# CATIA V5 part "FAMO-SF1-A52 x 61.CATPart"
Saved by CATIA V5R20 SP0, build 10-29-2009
Part number: FAMO-SF1-A52 x 61
Definition: NONE
Nomenclature: FAMO-SF1-A52 x 61
Source: Unknown
Description: FAMO-SF1-A52 x 61
Bounding box of the stored display mesh (mm): x -13 to 48, y -39.5 to 39.5, z -39.5 to 39.5
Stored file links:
  C:\Users\Utente\Desktop\IO LAVORO\3D X SITO CF\X SITO\FAMO\FAMO-SF1-A52 x 61.CATPart
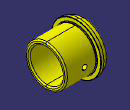
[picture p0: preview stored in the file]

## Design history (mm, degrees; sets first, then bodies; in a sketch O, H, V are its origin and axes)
Body1 "FAMO-SF1-A52 x 61" (main body)
  Solid1: solid without history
